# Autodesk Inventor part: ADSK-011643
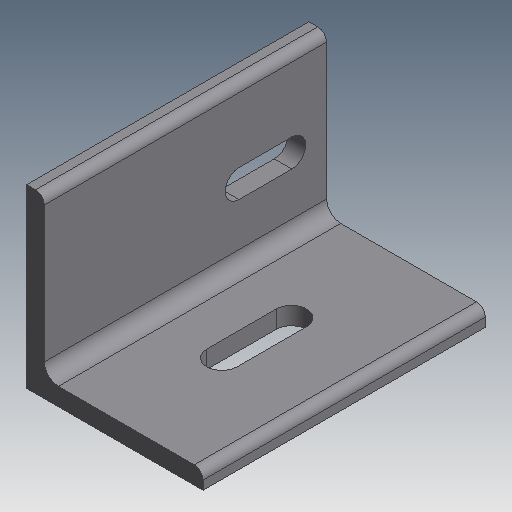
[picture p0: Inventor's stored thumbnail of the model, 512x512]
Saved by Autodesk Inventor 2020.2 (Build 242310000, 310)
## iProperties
Created: 2000-02
Part Number: ADSK-011643
Material: Pearson HRS
Document SubType Name: Modeling
Designer: sspink
Density: 7.83 g/cm^3
Appearance: Métal - Acier
Mass: 577.652 g
Surface Area: 265.158 cm^2
Volume: 73.7742 cm^3
Control State: 0
Checked Out: False
Master: False
Shininess: 0.0
Length Units: 11269
Angle Units: 11279
Time Units: 11290
Mass Units: 11283
Length Display Precision: 3
Angle Display Precision: 2
Compacted: True
Cutlength: 4
Material Desc: ANGLE,HRS,.250X2.50X2.50
Material_Number: A084057
Dimensions: 63,5x101,6x63,5 mm
Mass: 0,579 kg
VLT_Material: Pearson HRS
Density: 0.0
Volumn: 0.0
Area: 0.0
PropertySet Name: Model Information
Author: sspink
Revision Number: -
Title: ADSK-011643
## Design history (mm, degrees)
node "Element2:1"
node "Extrusion1" dims "d12" = 25.4, "d13" = 0
  sketch "Sketch3"
    geometry: L1 (0, 0)-(0, 101.6) reference; L2 (26.5, 38.3)-(37.5, 38.3); L3 (37.5, 38.3)-(37.5, 63.3); L4 (37.5, 63.3)-(26.5, 63.3); L5 (26.5, 63.3)-(26.5, 38.3); L6 (63.5, 0)-(63.5, 101.6) reference; A1 r 5.5 centre (32, 63.3) between (37.5, 63.3) and (26.5, 63.3); A2 r 5.5 centre (32, 38.3) between (26.5, 38.3) and (37.5, 38.3); 2 further points
    constraints: 8 end point, 4 point on circle, 2 centre point, 2 midpoint, 2 parallel, 2 tangent, 1 horizontal, 1 horizontal alignment, 1 perpendicular
    dimensions: "d8" = 25 distance of L4.end L2.start; "d9" = 11 distance of L3.end L4.end; "d11" = 32 distance from line of A2.centre L1
node "Extrusion2" dims "d18" = 25.4, "d19" = 0
  sketch "Sketch4"
    geometry: L1 (0, 63.5)-(0, 0) reference; L2 (0, 0)-(101.6, 0) reference; L3 (12.5, 37)-(31.5, 37); L4 (31.5, 37)-(31.5, 27); L5 (31.5, 27)-(12.5, 27); L6 (12.5, 27)-(12.5, 37); A1 r 5 centre (12.5, 32) between (12.5, 37) and (12.5, 27); A2 r 5 centre (31.5, 32) between (31.5, 27) and (31.5, 37)
    constraints: 8 end point, 4 point on circle, 2 centre point, 2 parallel, 2 tangent, 1 horizontal, 1 perpendicular
    dimensions: "d14" = 19 distance of L3.start L3.end; "d15" = 10 distance of L3.end L4.end; "d16" = 12.5 distance from line of A1.centre L1; "d17" = 32 distance from line of A1.centre L2
node "Solide1"
node "Corps solides"
node "Corps surfaciques"
sketch "Sketch2"
  geometry: L1 (32.408, 38.758)-(95.908, 38.758); L2 (32.408, 102.258)-(32.408, 38.758); L3 (38.758, 99.083)-(38.758, 50.188); L4 (43.838, 45.108)-(92.733, 45.108); L5 (32.408, 102.258)-(35.583, 102.258); L6 (95.908, 41.933)-(95.908, 38.758); A1 r 3.175 centre (35.583, 99.083) between (38.758, 99.083) and (35.583, 102.258); A2 r 3.175 centre (92.733, 41.933) between (95.908, 41.933) and (92.733, 45.108); A3 r 5.08 centre (43.838, 50.188) between (38.758, 50.188) and (43.838, 45.108); 1 further point
  constraints: 12 end point, 6 point on circle, 6 tangent, 3 centre point, 1 coincident, 1 equal radius, 1 horizontal, 1 perpendicular, 1 other
  dimensions: "d0" = 6.35 distance between parallel lines of L2 L3 (derived); "d6" = 3.175 radius of A1 (derived); "d7" = 5.08 radius of A3 (derived); "d2" = 63.5 distance between parallel lines of L1 L5 (derived); "d4" = 63.5 distance between parallel lines of L6 L2 (derived)
